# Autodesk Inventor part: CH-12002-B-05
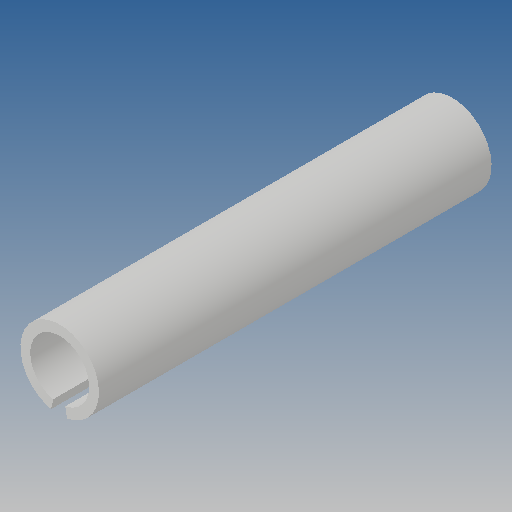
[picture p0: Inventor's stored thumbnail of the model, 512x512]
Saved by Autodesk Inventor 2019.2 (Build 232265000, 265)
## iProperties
Created: 2012-09
Part Number: CH-12002-B-05
Material: Ogólny
Document SubType Name: Modeling
Designer: CADENGINEERING4
Density: 1 g/cm^3
Appearance: Domyślna
Author: CADENGINEERING4
Revision Number: ÈÎºÎ
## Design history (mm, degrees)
feature "À­Éì1"
node "Bryła1"
